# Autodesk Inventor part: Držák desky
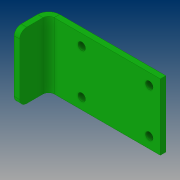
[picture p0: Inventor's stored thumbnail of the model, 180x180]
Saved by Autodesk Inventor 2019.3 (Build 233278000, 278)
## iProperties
Created: 2019-02
Part Number: Držák desky
Material: Ocel, legovaná
Document SubType Name: Plech
Designer: B-hon
Density: 7.73 g/cm^3
Sheet Metal Rule: Výchozí_mm
Appearance: Tmavě zelená
Author: B-hon
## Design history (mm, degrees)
node "Plocha1"
  sketch "Náčrt1"
    geometry: L1 (0, 0)-(85, 0); L2 (85, 0)-(85, 48); L3 (85, 48)-(0, 48); L4 (0, 48)-(0, 0)
    constraints: 8 end point, 2 parallel, 1 horizontal, 1 perpendicular
    dimensions: "d0" = 85 distance of L3.end L2.end; "d1" = 48 distance of L2.end L1.end
node "Obruba1"
sketch "Náčrt3"
  geometry: L1 (77, 40)-(28, 40); L2 (28, 40)-(28, 8); L3 (28, 8)-(77, 8); L4 (77, 8)-(77, 40); L5 (85, 0)-(8, 0) reference; L6 (85, 48)-(85, 0) reference; 5 further points
  constraints: 8 end point, 4 coincident, 2 parallel, 1 horizontal, 1 perpendicular
  dimensions: "d13" = 49 distance of L3.end L2.end; "d14" = 32 distance of L2.end L1.end; "d15" = 8 distance between parallel lines of L5 L3; "d16" = 8 distance between parallel lines of L6 L4
hole "Díra1" sketch "Náčrt3" at (28, 40), (77, 40), (77, 8), (28, 8) diameter "d17" = 5.5; stored, may be unused: countersink angle "d21" = 90 deg, drill point angle "d23" = 118 deg; dims "d18" = 6, "d19" = 4, "d20" = 2, "d22" = 4 (= Tloušťka)
fillet "Zaoblení1" dims "d24" = 5
node "Těleso1"
feature "Deska1" dims "d2" = 4 (= Tloušťka)
sketch "Náčrt2"
  geometry: L1 through (-24, 0) direction (1, 0); L2 through (0, 12.5) direction (-9.86e-33, 1); L3 (0, 25)-(-48, 25); L4 (-48, 25)-(-48, 0)
  constraints: 6 end point, 1 horizontal, 1 perpendicular, 1 vertical
feature "Deska2" dims "d2" = 4 (= Tloušťka), "d3" = 4 (= ŠířkaVýštipu), "d4" = 2 (= HloubkaVýštipu), "d5" = 8 (= MinimálníZbytek), "d6" = 4 (= PřechodovýPoloměr), "d7" = 25, "d8" = 90 deg, "d9" = 4 (= PoloměrOhybu), "d10" = 16 (= VelikostRohovéhoVýštipu), "d11" = 4 (= VelikostMezery), "d12" = 4 (= VelikostJacobihoPoloměru), "MezeraVystřižení" = 0.01
feature "Ohyb1" dims "d2" = 4 (= Tloušťka), "d3" = 4 (= ŠířkaVýštipu), "d4" = 2 (= HloubkaVýštipu), "d5" = 8 (= MinimálníZbytek), "d6" = 4 (= PřechodovýPoloměr), "d7" = 25, "d8" = 90 deg, "d9" = 4 (= PoloměrOhybu), "MezeraVystřižení" = 0.01
feature "Roh1" dims "d7" = 25, "d8" = 90 deg, "d10" = 16 (= VelikostRohovéhoVýštipu), "d11" = 4 (= VelikostMezery), "d12" = 4 (= VelikostJacobihoPoloměru)
other parameters: "Tloušťka" = 4 (derived), "KSoučinitel" = 4.4, "PoloměrOhybu" = 4 (= Tloušťka), "ŠířkaVýštipu" = 4 (= Tloušťka), "HloubkaVýštipu" = 2 (= 0.5 x Tloušťka), "VelikostRohovéhoVýštipu" = 16 (= 4 x Tloušťka), "MinimálníZbytek" = 8 (= 2 x Tloušťka), "PřechodovýPoloměr" = 4 (= PoloměrOhybu), "VelikostJacobihoPoloměru" = 4 (= PoloměrOhybu), "VelikostMezery" = 4 (= Tloušťka)
